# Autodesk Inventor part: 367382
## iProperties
Created: 2006-09
Part Number: 367382
Material: 8.8 vz
Description: Zylinderschraube
Vendor: Autodesk Inc.
Document SubType Name: Modeling
Standard: DIN 912
Designer: I.Baliuc
Standards Organization: DIN
Language: de-DE
Size Designation: M6 x 35
Categories: <MemberInstance Version="R10.0.0"><Categories><Category DisplayName="Schrauben" InternalName="e4da775c-781d-43d5-af7c-5136215cf5a6" Mnemonic="FSTN"><Category Di
Density: 7.85 g/cm^3
Abmessung: M6 x 35
Author: T.Messerschmitt
Comments: DIN 912 - M6 x 35
Revision Number: 367382
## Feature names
1. Körper [Revolution]
2. Loch [Extrusion]
3. Rundung1 [Fillet]
4. Fase1 [Chamfer]
